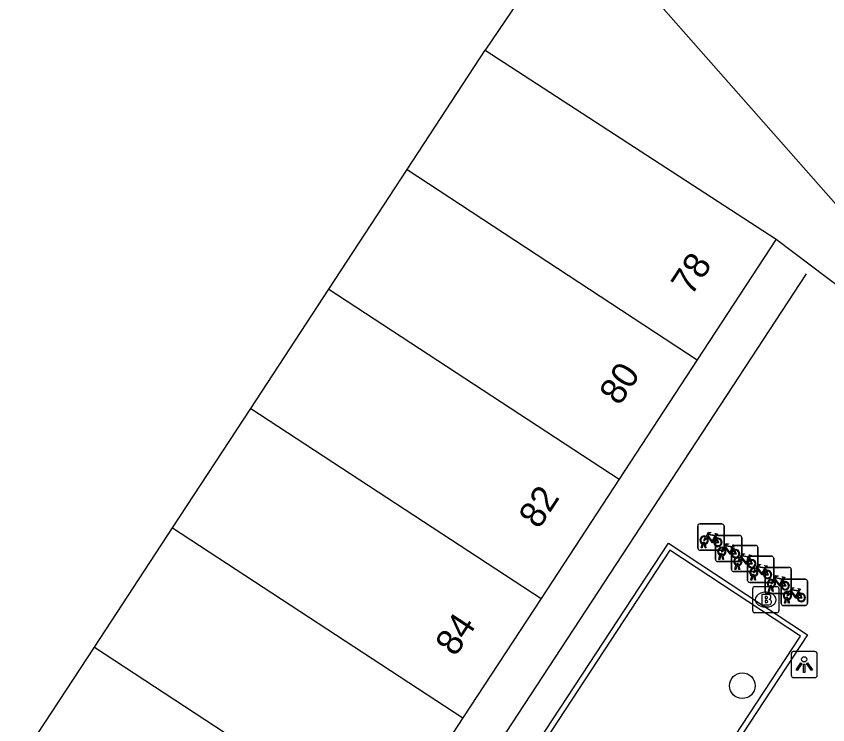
# Model space of a CAD drawing. Extents: x 155640 to 156810, y 382822 to 384046.
# Drawn here: x 156442.1 to 156473.07, y 383762.35 to 383789.39 of the extents above; entities that cross this region are included whole.
import ezdxf

# ---------------------------------------------------------------- set-up
doc = ezdxf.new("R2010")
doc.units = 0
for name, color, linetype in [('IMGEO_Boom', 7, 'Continuous'), ('IMGEO_Brandkraan', 7, 'Continuous'), ('IMGEO_Fietsenrek', 7, 'Continuous'), ('IMGEO_Lichtpunt', 7, 'Continuous'), ('IMGEO_Lijnafwatering', 7, 'Continuous'), ('IMGEO_Muur', 7, 'Continuous'), ('IMGEO_Pand', 7, 'Continuous'), ('IMGEO_Pand_nummerreeks', 7, 'Continuous'), ('IMGEO_Voetgangersgebied_open', 7, 'Continuous')]:
    doc.layers.add(name, color=color, linetype=linetype)

msp = doc.modelspace()

# ---------------------------------------------------------------- linework, layer by layer
at = {"layer": 'IMGEO_Boom'}
msp.add_circle((156469.813, 383763.841), 0.489, dxfattribs=at)
at = {"layer": 'IMGEO_Brandkraan'}
for p, q in [((156470.207, 383766.7), (156470.207, 383767.552)), ((156470.282, 383767.626), (156471.134, 383767.626)), ((156471.208, 383767.552), (156471.208, 383766.7)), ((156470.695, 383767.406), (156470.72, 383767.406)), ((156470.718, 383766.846), (156470.693, 383766.846)), ((156471.134, 383766.626), (156470.282, 383766.626))]:
    msp.add_line(p, q, dxfattribs=at)
for points in [[(156470.207, 383766.7), (156470.207, 383767.552)], [(156470.282, 383767.626), (156471.134, 383767.626)], [(156471.208, 383767.552), (156471.208, 383766.7)], [(156470.555, 383767.326), (156470.555, 383766.926), (156470.768, 383766.926)], [(156470.786, 383767.326), (156470.555, 383767.326)], [(156470.734, 383767.245), (156470.68, 383767.245), (156470.68, 383767.169)], [(156470.68, 383767.169), (156470.733, 383767.169)], [(156470.742, 383767.093), (156470.68, 383767.093), (156470.68, 383767.012)], [(156470.68, 383767.012), (156470.742, 383767.012)], [(156471.134, 383766.626), (156470.282, 383766.626)]]:
    msp.add_lwpolyline(points, dxfattribs=at)
for centre, radius, start, end in [((156470.284, 383767.55), 0.0765, 91.552, 178.448), ((156470.284, 383767.55), 0.0765, 91.552, 178.448), ((156471.132, 383767.55), 0.0765, 1.552, 88.448), ((156471.132, 383767.55), 0.0765, 1.552, 88.448), ((156470.735, 383767.207), 0.0379, 267.8285, 90.9355), ((156470.79, 383767.181), 0.145, 59.4692, 91.5367), ((156470.815, 383767.228), 0.0922, 285.5137, 58.1501), ((156470.82, 383767.036), 0.105, 301.3115, 78.989), ((156470.743, 383767.052), 0.0404, 269.8759, 90.5077), ((156470.774, 383767.177), 0.251, 268.6676, 293.5347), ((156470.284, 383766.702), 0.0765, 181.552, 268.448), ((156470.284, 383766.702), 0.0765, 181.552, 268.448), ((156471.132, 383766.702), 0.0765, 271.552, 358.448), ((156471.132, 383766.702), 0.0765, 271.552, 358.448)]:
    msp.add_arc(centre, radius, start, end, dxfattribs=at)
for centre, major_axis, ratio, start_param, end_param in [((156470.694, 383767.126), (-0.387, 0.002), 0.722429, 4.712389, 7.853982), ((156470.719, 383767.126), (-0.39, 0.002), 0.717154, 1.570796, 4.712389)]:
    msp.add_ellipse(centre, major_axis=major_axis, ratio=ratio, start_param=start_param, end_param=end_param, dxfattribs=at)
at = {"layer": 'IMGEO_Fietsenrek'}
for p, q in [((156468.113, 383769.089), (156468.113, 383769.93)), ((156468.113, 383769.93), (156468.113, 383769.089)), ((156468.188, 383770.014), (156469.029, 383770.014)), ((156469.029, 383770.014), (156468.188, 383770.014)), ((156469.113, 383769.939), (156469.113, 383769.098)), ((156469.113, 383769.098), (156469.113, 383769.939)), ((156468.351, 383769.27), (156468.35, 383769.274)), ((156468.382, 383769.281), (156468.383, 383769.274)), ((156468.787, 383768.654), (156468.787, 383769.495)), ((156468.787, 383769.495), (156468.787, 383768.654)), ((156468.8, 383769.563), (156468.836, 383769.468)), ((156468.862, 383769.579), (156469.703, 383769.579)), ((156469.703, 383769.579), (156468.862, 383769.579)), ((156469.787, 383769.504), (156469.787, 383768.663)), ((156469.787, 383768.663), (156469.787, 383769.504)), ((156469.038, 383769.014), (156468.197, 383769.014)), ((156468.197, 383769.014), (156469.038, 383769.014)), ((156468.24, 383769.098), (156468.279, 383769.258)), ((156468.274, 383769.098), (156468.24, 383769.098)), ((156468.309, 383769.246), (156468.274, 383769.098)), ((156468.392, 383769.098), (156468.358, 383769.24)), ((156468.39, 383769.244), (156468.425, 383769.098)), ((156468.425, 383769.098), (156468.392, 383769.098)), ((156469.404, 383768.271), (156469.404, 383769.112)), ((156469.404, 383769.112), (156469.404, 383768.271)), ((156469.474, 383769.128), (156469.51, 383769.033)), ((156469.479, 383769.196), (156470.32, 383769.196)), ((156470.32, 383769.196), (156469.479, 383769.196)), ((156470.404, 383769.121), (156470.404, 383768.28)), ((156470.404, 383768.28), (156470.404, 383769.121)), ((156468.914, 383768.663), (156468.953, 383768.823)), ((156468.948, 383768.663), (156468.914, 383768.663)), ((156468.983, 383768.811), (156468.948, 383768.663)), ((156469.025, 383768.835), (156469.024, 383768.839)), ((156469.066, 383768.663), (156469.032, 383768.805)), ((156469.056, 383768.846), (156469.057, 383768.839)), ((156469.064, 383768.809), (156469.099, 383768.663)), ((156469.099, 383768.663), (156469.066, 383768.663)), ((156470.009, 383767.86), (156470.009, 383768.701)), ((156470.009, 383768.701), (156470.009, 383767.86)), ((156470.084, 383768.785), (156470.925, 383768.785)), ((156470.925, 383768.785), (156470.084, 383768.785)), ((156470.091, 383768.745), (156470.127, 383768.65)), ((156471.009, 383768.71), (156471.009, 383767.869)), ((156471.009, 383767.869), (156471.009, 383768.71)), ((156469.712, 383768.579), (156468.871, 383768.579)), ((156468.871, 383768.579), (156469.712, 383768.579)), ((156469.531, 383768.28), (156469.57, 383768.44)), ((156469.6, 383768.428), (156469.565, 383768.28)), ((156469.642, 383768.452), (156469.641, 383768.456)), ((156469.683, 383768.28), (156469.649, 383768.422)), ((156469.673, 383768.463), (156469.674, 383768.456)), ((156469.681, 383768.426), (156469.716, 383768.28)), ((156470.756, 383768.356), (156471.597, 383768.356)), ((156471.597, 383768.356), (156470.756, 383768.356)), ((156470.329, 383768.196), (156469.488, 383768.196)), ((156469.488, 383768.196), (156470.329, 383768.196)), ((156469.565, 383768.28), (156469.531, 383768.28)), ((156469.716, 383768.28), (156469.683, 383768.28)), ((156470.247, 383768.041), (156470.246, 383768.045)), ((156470.278, 383768.052), (156470.279, 383768.045)), ((156470.681, 383767.431), (156470.681, 383768.272)), ((156470.681, 383768.272), (156470.681, 383767.431)), ((156470.696, 383768.334), (156470.732, 383768.239)), ((156471.681, 383768.281), (156471.681, 383767.44)), ((156471.681, 383767.44), (156471.681, 383768.281)), ((156470.934, 383767.785), (156470.093, 383767.785)), ((156470.093, 383767.785), (156470.934, 383767.785)), ((156470.136, 383767.869), (156470.175, 383768.029)), ((156470.17, 383767.869), (156470.136, 383767.869)), ((156470.205, 383768.017), (156470.17, 383767.869)), ((156470.288, 383767.869), (156470.254, 383768.011)), ((156470.286, 383768.015), (156470.321, 383767.869)), ((156470.321, 383767.869), (156470.288, 383767.869)), ((156471.295, 383766.979), (156471.295, 383767.82)), ((156471.295, 383767.82), (156471.295, 383766.979)), ((156471.368, 383767.905), (156471.404, 383767.81)), ((156471.37, 383767.904), (156472.211, 383767.904)), ((156472.211, 383767.904), (156471.37, 383767.904)), ((156472.295, 383767.829), (156472.295, 383766.988)), ((156472.295, 383766.988), (156472.295, 383767.829)), ((156470.808, 383767.44), (156470.847, 383767.6)), ((156470.842, 383767.44), (156470.808, 383767.44)), ((156470.877, 383767.588), (156470.842, 383767.44)), ((156470.919, 383767.612), (156470.918, 383767.616)), ((156470.96, 383767.44), (156470.926, 383767.582)), ((156470.95, 383767.623), (156470.951, 383767.616)), ((156470.958, 383767.586), (156470.993, 383767.44)), ((156470.993, 383767.44), (156470.96, 383767.44)), ((156471.982, 383767.453), (156472.018, 383767.358)), ((156471.606, 383767.356), (156470.765, 383767.356)), ((156470.765, 383767.356), (156471.606, 383767.356)), ((156471.422, 383766.988), (156471.461, 383767.148)), ((156471.491, 383767.136), (156471.456, 383766.988)), ((156471.533, 383767.16), (156471.532, 383767.164)), ((156471.574, 383766.988), (156471.54, 383767.13)), ((156471.564, 383767.171), (156471.565, 383767.164)), ((156471.572, 383767.134), (156471.607, 383766.988)), ((156472.22, 383766.904), (156471.379, 383766.904)), ((156471.379, 383766.904), (156472.22, 383766.904)), ((156471.456, 383766.988), (156471.422, 383766.988)), ((156471.607, 383766.988), (156471.574, 383766.988))]:
    msp.add_line(p, q, dxfattribs=at)
for points in [[(156468.426, 383769.54), (156468.521, 383769.704), (156468.607, 383769.69), (156468.609, 383769.681), (156468.553, 383769.67), (156468.526, 383769.625), (156468.782, 383769.584)], [(156468.769, 383769.559), (156468.512, 383769.6), (156468.495, 383769.571), (156468.662, 383769.351), (156468.769, 383769.559)], [(156468.782, 383769.584), (156468.807, 383769.633), (156468.801, 383769.637), (156468.778, 383769.641), (156468.766, 383769.648), (156468.765, 383769.651), (156468.767, 383769.656), (156468.862, 383769.641), (156468.864, 383769.631), (156468.854, 383769.618), (156468.842, 383769.612), (156468.828, 383769.618), (156468.8, 383769.563)], [(156468.447, 383769.488), (156468.395, 383769.398), (156468.355, 383769.373), (156468.356, 383769.42), (156468.411, 383769.514)], [(156468.722, 383769.296), (156468.672, 383769.296), (156468.481, 383769.547), (156468.462, 383769.515)], [(156468.817, 383769.461), (156468.787, 383769.538), (156468.678, 383769.32), (156468.721, 383769.32)], [(156468.751, 383769.32), (156468.871, 383769.319), (156468.827, 383769.433)], [(156468.847, 383769.44), (156468.902, 383769.295), (156468.752, 383769.295)], [(156469.121, 383769.053), (156469.069, 383768.963), (156469.029, 383768.938), (156469.03, 383768.985), (156469.085, 383769.079)], [(156469.1, 383769.105), (156469.195, 383769.269), (156469.281, 383769.255), (156469.283, 383769.246), (156469.227, 383769.235), (156469.2, 383769.19), (156469.456, 383769.149)], [(156469.396, 383768.861), (156469.346, 383768.861), (156469.155, 383769.112), (156469.136, 383769.08)], [(156469.443, 383769.124), (156469.186, 383769.165), (156469.169, 383769.136), (156469.336, 383768.916), (156469.443, 383769.124)], [(156469.491, 383769.026), (156469.461, 383769.103), (156469.352, 383768.885), (156469.395, 383768.885)], [(156469.425, 383768.885), (156469.545, 383768.884), (156469.501, 383768.998)], [(156469.521, 383769.005), (156469.576, 383768.86), (156469.426, 383768.86)], [(156469.456, 383769.149), (156469.481, 383769.198), (156469.475, 383769.202), (156469.452, 383769.206), (156469.44, 383769.213), (156469.439, 383769.216), (156469.441, 383769.221), (156469.536, 383769.206), (156469.538, 383769.196), (156469.528, 383769.183), (156469.516, 383769.177), (156469.502, 383769.183), (156469.474, 383769.128)], [(156469.738, 383768.67), (156469.686, 383768.58), (156469.646, 383768.555), (156469.647, 383768.602), (156469.702, 383768.696)], [(156469.717, 383768.722), (156469.812, 383768.886), (156469.898, 383768.872), (156469.9, 383768.863), (156469.844, 383768.852), (156469.817, 383768.807), (156470.073, 383768.766)], [(156470.013, 383768.478), (156469.963, 383768.478), (156469.772, 383768.729), (156469.753, 383768.697)], [(156470.06, 383768.741), (156469.803, 383768.782), (156469.786, 383768.753), (156469.953, 383768.533), (156470.06, 383768.741)], [(156470.108, 383768.643), (156470.078, 383768.72), (156469.969, 383768.502), (156470.012, 383768.502)], [(156470.073, 383768.766), (156470.098, 383768.815), (156470.092, 383768.819), (156470.069, 383768.823), (156470.057, 383768.83), (156470.056, 383768.833), (156470.058, 383768.838), (156470.153, 383768.823), (156470.155, 383768.813), (156470.145, 383768.8), (156470.133, 383768.794), (156470.119, 383768.8), (156470.091, 383768.745)], [(156470.042, 383768.502), (156470.162, 383768.501), (156470.118, 383768.615)], [(156470.138, 383768.622), (156470.193, 383768.477), (156470.043, 383768.477)], [(156470.322, 383768.311), (156470.417, 383768.475), (156470.503, 383768.461), (156470.505, 383768.452), (156470.449, 383768.441), (156470.422, 383768.396), (156470.678, 383768.355)], [(156470.665, 383768.33), (156470.408, 383768.371), (156470.391, 383768.342), (156470.558, 383768.122), (156470.665, 383768.33)], [(156470.678, 383768.355), (156470.703, 383768.404), (156470.697, 383768.408), (156470.674, 383768.412), (156470.662, 383768.419), (156470.661, 383768.422), (156470.663, 383768.427), (156470.758, 383768.412), (156470.76, 383768.402), (156470.75, 383768.389), (156470.738, 383768.383), (156470.724, 383768.389), (156470.696, 383768.334)], [(156470.343, 383768.259), (156470.291, 383768.169), (156470.251, 383768.144), (156470.252, 383768.191), (156470.307, 383768.285)], [(156470.618, 383768.067), (156470.568, 383768.067), (156470.377, 383768.318), (156470.358, 383768.286)], [(156470.713, 383768.232), (156470.683, 383768.309), (156470.574, 383768.091), (156470.617, 383768.091)], [(156470.647, 383768.091), (156470.767, 383768.09), (156470.723, 383768.204)], [(156470.743, 383768.211), (156470.798, 383768.066), (156470.648, 383768.066)], [(156470.994, 383767.882), (156471.089, 383768.046), (156471.175, 383768.032), (156471.177, 383768.023), (156471.121, 383768.012), (156471.094, 383767.967), (156471.35, 383767.926)], [(156471.015, 383767.83), (156470.963, 383767.74), (156470.923, 383767.715), (156470.924, 383767.762), (156470.979, 383767.856)], [(156471.29, 383767.638), (156471.24, 383767.638), (156471.049, 383767.889), (156471.03, 383767.857)], [(156471.337, 383767.901), (156471.08, 383767.942), (156471.063, 383767.913), (156471.23, 383767.693), (156471.337, 383767.901)], [(156471.385, 383767.803), (156471.355, 383767.88), (156471.246, 383767.662), (156471.289, 383767.662)], [(156471.319, 383767.662), (156471.439, 383767.661), (156471.395, 383767.775)], [(156471.415, 383767.782), (156471.47, 383767.637), (156471.32, 383767.637)], [(156471.35, 383767.926), (156471.375, 383767.975), (156471.369, 383767.979), (156471.346, 383767.983), (156471.334, 383767.99), (156471.333, 383767.993), (156471.335, 383767.998), (156471.43, 383767.983), (156471.432, 383767.973), (156471.422, 383767.96), (156471.41, 383767.954), (156471.396, 383767.96), (156471.368, 383767.905)], [(156471.608, 383767.43), (156471.703, 383767.594), (156471.789, 383767.58), (156471.791, 383767.571), (156471.735, 383767.56), (156471.708, 383767.515), (156471.964, 383767.474)], [(156471.904, 383767.186), (156471.854, 383767.186), (156471.663, 383767.437), (156471.644, 383767.405)], [(156471.951, 383767.449), (156471.694, 383767.49), (156471.677, 383767.461), (156471.844, 383767.241), (156471.951, 383767.449)], [(156471.999, 383767.351), (156471.969, 383767.428), (156471.86, 383767.21), (156471.903, 383767.21)], [(156471.964, 383767.474), (156471.989, 383767.523), (156471.983, 383767.527), (156471.96, 383767.531), (156471.948, 383767.538), (156471.947, 383767.541), (156471.949, 383767.546), (156472.044, 383767.531), (156472.046, 383767.521), (156472.036, 383767.508), (156472.024, 383767.502), (156472.01, 383767.508), (156471.982, 383767.453)], [(156471.629, 383767.378), (156471.577, 383767.288), (156471.537, 383767.263), (156471.538, 383767.31), (156471.593, 383767.404)], [(156471.933, 383767.21), (156472.053, 383767.209), (156472.009, 383767.323)], [(156472.029, 383767.33), (156472.084, 383767.185), (156471.934, 383767.185)]]:
    msp.add_lwpolyline(points, dxfattribs=at)
for centre, radius, start, end in [((156468.191, 383769.936), 0.0779, 92.4484, 184.2845), ((156468.191, 383769.936), 0.0779, 92.4484, 184.2845), ((156469.035, 383769.936), 0.0779, 2.4484, 94.2845), ((156469.035, 383769.936), 0.0779, 2.4484, 94.2845), ((156468.353, 383769.399), 0.159, 62.6766, 242.1369), ((156468.353, 383769.399), 0.129, 63.3192, 238.903), ((156468.333, 383769.27), 0.0499, 12.8025, 158.6934), ((156468.333, 383769.27), 0.0174, 12.8025, 163.4502), ((156468.353, 383769.399), 0.129, 253.415, 269.0204), ((156468.353, 383769.399), 0.129, 283.6043, 43.4302), ((156468.353, 383769.399), 0.159, 283.5766, 46.6042), ((156468.88, 383769.315), 0.159, 113.3408, 178.3217), ((156468.88, 383769.315), 0.159, 187.0065, 105.7708), ((156468.88, 383769.315), 0.129, 113.923, 177.9556), ((156468.88, 383769.315), 0.129, 188.6715, 104.5883), ((156468.865, 383769.501), 0.0779, 92.4484, 184.2845), ((156468.865, 383769.501), 0.0779, 92.4484, 184.2845), ((156469.709, 383769.501), 0.0779, 2.4484, 94.2845), ((156469.709, 383769.501), 0.0779, 2.4484, 94.2845), ((156468.191, 383769.092), 0.0779, 182.4484, 274.2845), ((156468.191, 383769.092), 0.0779, 182.4484, 274.2845), ((156468.353, 383769.399), 0.159, 253.9967, 271.7867), ((156469.027, 383768.964), 0.159, 62.6766, 242.1369), ((156469.027, 383768.964), 0.129, 63.3192, 238.903), ((156469.035, 383769.092), 0.0779, 272.4484, 4.2845), ((156469.035, 383769.092), 0.0779, 272.4484, 4.2845), ((156469.027, 383768.964), 0.129, 283.6043, 43.4302), ((156469.027, 383768.964), 0.159, 283.5766, 46.6042), ((156469.554, 383768.88), 0.159, 113.3408, 178.3217), ((156469.554, 383768.88), 0.159, 187.0065, 105.7708), ((156469.482, 383769.118), 0.0779, 92.4484, 184.2845), ((156469.482, 383769.118), 0.0779, 92.4484, 184.2845), ((156469.554, 383768.88), 0.129, 113.923, 177.9556), ((156469.554, 383768.88), 0.129, 188.6715, 104.5883), ((156470.326, 383769.118), 0.0779, 2.4484, 94.2845), ((156470.326, 383769.118), 0.0779, 2.4484, 94.2845), ((156468.865, 383768.657), 0.0779, 182.4484, 274.2845), ((156468.865, 383768.657), 0.0779, 182.4484, 274.2845), ((156469.007, 383768.835), 0.0499, 12.8025, 158.6934), ((156469.027, 383768.964), 0.159, 253.9967, 271.7867), ((156469.007, 383768.835), 0.0174, 12.8025, 163.4502), ((156469.027, 383768.964), 0.129, 253.415, 269.0204), ((156469.644, 383768.581), 0.159, 62.6766, 242.1369), ((156469.644, 383768.581), 0.129, 63.3192, 238.903), ((156469.644, 383768.581), 0.129, 283.6043, 43.4302), ((156469.644, 383768.581), 0.159, 283.5766, 46.6042), ((156469.709, 383768.657), 0.0779, 272.4484, 4.2845), ((156469.709, 383768.657), 0.0779, 272.4484, 4.2845), ((156470.087, 383768.707), 0.0779, 92.4484, 184.2845), ((156470.087, 383768.707), 0.0779, 92.4484, 184.2845), ((156470.171, 383768.497), 0.159, 187.0065, 105.7708), ((156470.931, 383768.707), 0.0779, 2.4484, 94.2845), ((156470.931, 383768.707), 0.0779, 2.4484, 94.2845), ((156469.624, 383768.452), 0.0499, 12.8025, 158.6934), ((156469.644, 383768.581), 0.159, 253.9967, 271.7867), ((156469.624, 383768.452), 0.0174, 12.8025, 163.4502), ((156469.644, 383768.581), 0.129, 253.415, 269.0204), ((156470.171, 383768.497), 0.159, 113.3408, 178.3217), ((156470.171, 383768.497), 0.129, 113.923, 177.9556), ((156470.171, 383768.497), 0.129, 188.6715, 104.5883), ((156470.759, 383768.278), 0.0779, 92.4484, 184.2845), ((156470.759, 383768.278), 0.0779, 92.4484, 184.2845), ((156471.603, 383768.278), 0.0779, 2.4484, 94.2845), ((156471.603, 383768.278), 0.0779, 2.4484, 94.2845), ((156469.482, 383768.274), 0.0779, 182.4484, 274.2845), ((156469.482, 383768.274), 0.0779, 182.4484, 274.2845), ((156470.249, 383768.17), 0.159, 62.6766, 242.1369), ((156470.249, 383768.17), 0.129, 63.3192, 238.903), ((156470.229, 383768.041), 0.0499, 12.8025, 158.6934), ((156470.229, 383768.041), 0.0174, 12.8025, 163.4502), ((156470.249, 383768.17), 0.129, 253.415, 269.0204), ((156470.249, 383768.17), 0.129, 283.6043, 43.4302), ((156470.249, 383768.17), 0.159, 283.5766, 46.6042), ((156470.326, 383768.274), 0.0779, 272.4484, 4.2845), ((156470.326, 383768.274), 0.0779, 272.4484, 4.2845), ((156470.776, 383768.086), 0.159, 113.3408, 178.3217), ((156470.776, 383768.086), 0.159, 187.0065, 105.7708), ((156470.776, 383768.086), 0.129, 113.923, 177.9556), ((156470.776, 383768.086), 0.129, 188.6715, 104.5883), ((156470.087, 383767.863), 0.0779, 182.4484, 274.2845), ((156470.087, 383767.863), 0.0779, 182.4484, 274.2845), ((156470.249, 383768.17), 0.159, 253.9967, 271.7867), ((156470.921, 383767.741), 0.159, 62.6766, 242.1369), ((156470.921, 383767.741), 0.129, 63.3192, 238.903), ((156470.931, 383767.863), 0.0779, 272.4484, 4.2845), ((156470.931, 383767.863), 0.0779, 272.4484, 4.2845), ((156470.921, 383767.741), 0.129, 283.6043, 43.4302), ((156470.921, 383767.741), 0.159, 283.5766, 46.6042), ((156471.448, 383767.657), 0.159, 113.3408, 178.3217), ((156471.448, 383767.657), 0.159, 187.0065, 105.7708), ((156471.373, 383767.826), 0.0779, 92.4484, 184.2845), ((156471.373, 383767.826), 0.0779, 92.4484, 184.2845), ((156471.448, 383767.657), 0.129, 113.923, 177.9556), ((156471.448, 383767.657), 0.129, 188.6715, 104.5883), ((156472.217, 383767.826), 0.0779, 2.4484, 94.2845), ((156472.217, 383767.826), 0.0779, 2.4484, 94.2845), ((156470.759, 383767.434), 0.0779, 182.4484, 274.2845), ((156470.759, 383767.434), 0.0779, 182.4484, 274.2845), ((156470.901, 383767.612), 0.0499, 12.8025, 158.6934), ((156470.921, 383767.741), 0.159, 253.9967, 271.7867), ((156470.901, 383767.612), 0.0174, 12.8025, 163.4502), ((156470.921, 383767.741), 0.129, 253.415, 269.0204), ((156471.535, 383767.289), 0.159, 62.6766, 242.1369), ((156471.535, 383767.289), 0.129, 63.3192, 238.903), ((156471.603, 383767.434), 0.0779, 272.4484, 4.2845), ((156471.603, 383767.434), 0.0779, 272.4484, 4.2845), ((156471.515, 383767.16), 0.0499, 12.8025, 158.6934), ((156471.535, 383767.289), 0.159, 253.9967, 271.7867), ((156471.515, 383767.16), 0.0174, 12.8025, 163.4502), ((156471.535, 383767.289), 0.129, 253.415, 269.0204), ((156471.535, 383767.289), 0.129, 283.6043, 43.4302), ((156471.535, 383767.289), 0.159, 283.5766, 46.6042), ((156472.062, 383767.205), 0.159, 113.3408, 178.3217), ((156472.062, 383767.205), 0.159, 187.0065, 105.7708), ((156472.062, 383767.205), 0.129, 113.923, 177.9556), ((156472.062, 383767.205), 0.129, 188.6715, 104.5883), ((156471.373, 383766.982), 0.0779, 182.4484, 274.2845), ((156471.373, 383766.982), 0.0779, 182.4484, 274.2845), ((156472.217, 383766.982), 0.0779, 272.4484, 4.2845), ((156472.217, 383766.982), 0.0779, 272.4484, 4.2845)]:
    msp.add_arc(centre, radius, start, end, dxfattribs=at)
at = {"layer": 'IMGEO_Lichtpunt'}
for p, q in [((156471.676, 383765.05), (156471.676, 383764.243)), ((156471.676, 383765.05), (156471.676, 383764.243)), ((156472.578, 383765.145), (156471.77, 383765.145)), ((156472.578, 383765.145), (156471.77, 383765.145)), ((156472.672, 383764.243), (156472.672, 383765.05)), ((156472.672, 383764.243), (156472.672, 383765.05)), ((156471.77, 383764.149), (156472.578, 383764.149)), ((156471.77, 383764.149), (156472.578, 383764.149))]:
    msp.add_line(p, q, dxfattribs=at)
for points in [[(156472.05, 383764.714), (156472.089, 383764.686), (156471.901, 383764.424), (156471.863, 383764.451), (156472.05, 383764.714)], [(156472.152, 383764.666), (156472.199, 383764.666), (156472.199, 383764.344), (156472.152, 383764.344), (156472.152, 383764.666)], [(156472.262, 383764.686), (156472.3, 383764.713), (156472.487, 383764.451), (156472.448, 383764.423), (156472.262, 383764.686)]]:
    msp.add_lwpolyline(points, dxfattribs=at)
msp.add_circle((156472.175, 383764.848), 0.0994, dxfattribs=at)
for centre, start, end in [((156471.77, 383765.05), 90, 180), ((156471.77, 383765.05), 90, 180), ((156472.578, 383765.05), 0, 90), ((156472.578, 383765.05), 0, 90), ((156471.77, 383764.243), 180, 270), ((156471.77, 383764.243), 180, 270), ((156472.578, 383764.243), 270, 0), ((156472.578, 383764.243), 270, 360)]:
    msp.add_arc(centre, 0.0946, start, end, dxfattribs=at)
at = {"layer": 'IMGEO_Lijnafwatering'}
msp.add_lwpolyline([(156472.253, 383779.565), (156460.088, 383760.982)], dxfattribs=at)
at = {"layer": 'IMGEO_Muur'}
for points in [[(156464.303, 383753.596), (156458.99, 383757.098), (156466.993, 383769.287), (156472.306, 383765.783), (156464.303, 383753.596)], [(156464.246, 383753.873), (156472.029, 383765.726), (156467.05, 383769.009), (156459.267, 383757.155), (156464.246, 383753.873)]]:
    msp.add_lwpolyline(points, dxfattribs=at)
at = {"layer": 'IMGEO_Pand'}
for points in [[(156502.946, 383814.998), (156503.408, 383814.467), (156496.224, 383808.207), (156499.367, 383804.6), (156473.48, 383782.1), (156463.557, 383793.358)], [(156457.017, 383783.537), (156460.001, 383788.093)], [(156460.001, 383788.093), (156471.098, 383780.883)], [(156454.033, 383778.982), (156457.017, 383783.537)], [(156457.017, 383783.537), (156468.09, 383776.284)], [(156471.098, 383780.883), (156468.09, 383776.284)], [(156451.049, 383774.426), (156454.033, 383778.982)], [(156454.033, 383778.982), (156465.11, 383771.726)], [(156468.09, 383776.284), (156465.11, 383771.726)], [(156448.065, 383769.871), (156451.049, 383774.426)], [(156451.049, 383774.426), (156462.129, 383767.169)], [(156465.11, 383771.726), (156462.129, 383767.169)], [(156445.081, 383765.315), (156448.065, 383769.871)], [(156448.065, 383769.871), (156459.148, 383762.611)], [(156462.129, 383767.169), (156459.148, 383762.611)], [(156442.097, 383760.76), (156445.081, 383765.315)], [(156445.081, 383765.315), (156456.167, 383758.053)], [(156459.148, 383762.611), (156456.167, 383758.053)]]:
    msp.add_lwpolyline(points, dxfattribs=at)
at = {"layer": 'IMGEO_Voetgangersgebied_open'}
for points in [[(156463.557, 383793.358), (156460.001, 383788.093)], [(156471.098, 383780.883), (156477.589, 383775.981)]]:
    msp.add_lwpolyline(points, dxfattribs=at)

# ---------------------------------------------------------------- texts
at = {"layer": 'IMGEO_Pand_nummerreeks'}
for s, p in [('78', (156467.864, 383778.683)), ('80', (156465.124, 383774.494)), ('82', (156462.045, 383769.786)), ('84', (156458.862, 383764.92))]:
    msp.add_text(s, height=1, rotation=56.6197, dxfattribs=at).set_placement(p)

doc.saveas('drawing.dxf')
